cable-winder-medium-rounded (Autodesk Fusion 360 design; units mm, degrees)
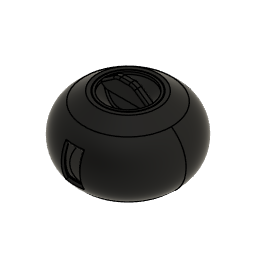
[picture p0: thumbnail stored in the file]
parameter "radius" = 30
parameter "height" = 40
parameter "gap" = 0.35
sketch "Skizze" plane through (0, 0, 0) normal (0, 1, 0) x axis (1, 0, 0)
  line L1 (30, 0) -> (0, 0)
  line L2 (14, -20) -> (16, -20)
  line L3 (14, -18.9589) -> (22, -13.3572)
  line L4 (14, -18.9589) -> (14, -20)
  line L5 (12.45, -20) -> (13.65, -20)
  line L6 (13.65, -18.7767) -> (13.65, -20)
  line L7 (15.6652, -17.3656) -> (13.65, -18.7767)
  line L8 (8, -11.9984) -> (15.6652, -17.3656)
  line L9 (8, 0) -> (8, -11.9984)
  line L10 (12.45, -18.7767) -> (12.45, -20)
  line L11 (5.626, -13.9984) -> (12.45, -18.7767)
  line L12 (0, -13.9984) -> (5.626, -13.9984)
  line L13 (12.45, -18.7767) -> (13.65, -18.7767)
  line L14 (0, 0) -> (0, -13.9984)
  line L15 (0, -20) -> (0, -13.9984)
  line L16 (12.45, -20) -> (0, -20)
  line L17 (0, -11.9984) -> (8, -11.9984)
  line L18 (15.3795, -17.1656) -> (15.3795, -17.5656)
  line L19 (0, 0) -> (0, 13.9984)
  line L20 (0, 11.9984) -> (8, 11.9984)
  line L21 (8, 0) -> (8, 11.9984)
  line L22 (8, 11.9984) -> (15.6652, 17.3656)
  line L23 (12.45, 20) -> (13.65, 20)
  line L24 (0, 20) -> (0, 13.9984)
  line L25 (12.45, 20) -> (0, 20)
  line L26 (13.65, 18.7767) -> (13.65, 20)
  line L27 (15.6652, 17.3656) -> (13.65, 18.7767)
  line L28 (14, 18.9589) -> (14, 20)
  line L29 (14, 20) -> (16, 20)
  line L30 (14, 18.9589) -> (22, 13.3572)
  line L31 (-2, -13.9984) -> (2, -13.9984)
  line L32 (4.4501, -25.6016) -> (12.45, -20)
  line L33 (0, -25.6016) -> (4.4501, -25.6016)
  line L34 (12.45, 18.7767) -> (12.45, 20)
  line L35 (5.626, 13.9984) -> (12.45, 18.7767)
  line L36 (0, 13.9984) -> (5.626, 13.9984)
  line L37 (-4.4501, -25.6016) -> (-12.45, -20)
  line L38 (0, -25.6016) -> (-4.4501, -25.6016)
  line L39 (-5.626, -13.9984) -> (-12.45, -18.7767)
  line L40 (-12.45, -18.7767) -> (-12.45, -20)
  line L41 (0, -13.9984) -> (-5.626, -13.9984)
  line L42 (0, 13.9984) -> (-5.626, 13.9984)
  line L43 (-5.626, 13.9984) -> (-12.45, 18.7767)
  line L44 (-12.45, 18.7767) -> (-12.45, 20)
  line L45 (-12.45, 20) -> (0, 20)
  line L46 (4, -8) -> (-4, -8)
  line L47 (4, 8) -> (4, -8)
  line L48 (-4, 8) -> (4, 8)
  line L49 (-4, -8) -> (-4, 8)
  line L50 (4, 8) -> (-4, -8)
  line L51 (-4, 8) -> (4, -8)
  curve K1 (22, 13.3572) -> (22, -13.3572)
  line L52 (16, -20) -> (23.1472, -14.9955)
  curve K2 (23.1472, 14.9955) -> (23.1472, -14.9955)
  line L53 (16, 20) -> (23.1472, 14.9955)
  point P1 (0, 0)
  point P2 (0, 0)
  point P12 (8, 0)
  point P17 (0, 0)
  point P19 (0, -11.9984)
  point P20 (15.3795, -17.5656)
  point P21 (15.3795, -17.1656)
  point P24 (0, 0)
  point P28 (0, 0)
  point P4 (16, -20)
  point P37 (16, 20)
  point P5 (22, -13.3572)
  point P38 (22, 13.3572)
  point P6 (14, -20)
  point P35 (14, 20)
  point P7 (14, -18.9589)
  point P36 (14, 18.9589)
  point P8 (13.65, -20)
  point P31 (13.65, 20)
  point P9 (13.65, -18.7767)
  point P34 (13.65, 18.7767)
  point P10 (15.6652, -17.3656)
  point P30 (15.6652, 17.3656)
  point P11 (8, -11.9984)
  point P23 (8, 11.9984)
  point P29 (8, 0)
  point P13 (12.45, -20)
  point P32 (12.45, 20)
  point P15 (5.626, -13.9984)
  point P27 (5.626, 13.9984)
  point P16 (0, -13.9984)
  point P22 (0, 13.9984)
  point P26 (0, 0)
  point P18 (0, -20)
  point P33 (0, 20)
  point P25 (0, 11.9984)
  point P41 (0, -20)
  point P44 (12.45, 20)
  point P14 (12.45, -18.7767)
  point P45 (12.45, 18.7767)
  point P46 (5.626, 13.9984)
  point P47 (0, 13.9984)
  point P48 (-12.45, -20)
  point P51 (-12.45, -18.7767)
  point P52 (-5.626, -13.9984)
  point P53 (0, -13.9984)
  point P42 (4.4501, -25.6016)
  point P49 (-4.4501, -25.6016)
  point P43 (0, -25.6016)
  point P50 (0, -25.6016)
  point P59 (-12.45, 20)
  point P58 (0, 20)
  point P57 (-12.45, 20)
  point P56 (-12.45, 18.7767)
  point P54 (-5.626, 13.9984)
  point P55 (0, 13.9984)
  point P64 (0, 0)
  point P3 (30, 0)
  point P62 (4, 8)
  point P63 (-4, 8)
  point P61 (4, -8)
  coincident P1 P2
  horizontal L1
  perpendicular L2 L4
  perpendicular L4 L5
  perpendicular L5 L6
  parallel L3 L7
  coincident L1 P12
  perpendicular L1 L9
  perpendicular L5 L10
  parallel L8 L11
  horizontal L13
  collinear L2 L5
  coincident P1 P17
  perpendicular L1 L14
  perpendicular L5 L15
  perpendicular L10 L16
  coincident L14 P19
  perpendicular L14 L17
  coincident L7 P20
  coincident L8 P21
  vertical L18
  symmetric P1 L1 P24
  symmetric P2 L1 P28
  symmetric L1 P4 P37
  symmetric L1 P5 P38
  symmetric L1 P6 P35
  symmetric L1 P7 P36
  symmetric L1 P8 P31
  symmetric L1 P9 P34
  symmetric L1 P10 P30
  symmetric L1 P11 P23
  symmetric L1 P12 P29
  symmetric L1 P13 P32
  symmetric L1 P15 P27
  symmetric L1 P16 P22
  symmetric L1 P17 P26
  symmetric L1 P18 P33
  symmetric L1 P19 P25
  horizontal L31
  coincident P18 P41
  collinear L12 L31
  perpendicular L15 L33
  symmetric L1 P13 P44
  symmetric L1 P14 P45
  symmetric L1 P15 P46
  symmetric L1 P16 P47
  symmetric P13 L15 P48
  symmetric P14 L15 P51
  symmetric P15 L15 P52
  symmetric P16 L15 P53
  symmetric L15 P42 P49
  symmetric L15 P43 P50
  symmetric P32 L24 P59
  symmetric P33 L24 P58
  symmetric L24 P44 P57
  symmetric L24 P45 P56
  symmetric L24 P46 P54
  symmetric L24 P47 P55
  horizontal L46
  perpendicular L46 L47
  parallel L46 L48
  parallel L47 L49
  coincident L50 P64
  coincident L51 P64
  coincident P28 P64
  dimension "d43" distance P2 P3 = 30 (= "radius")
  dimension "d49" distance P4 L4 = 2
  dimension "d50" distance L4 L6 = 0.35 (= "gap")
  dimension "d51" distance L3 L7 = 0.35 (= "d50")
  dimension "d52" angle L1 L8 = 35
  dimension "d54" distance L8 L11 = 3
  dimension "d55" distance P8 P13 = 1.2
  dimension "d57" distance P4 P16 = 16
  dimension "d58" distance L1 L16 = 20 (= "height / 2")
  dimension "d59" distance L12 L17 = 2
  dimension "d60" distance P20 P21 = 0.4
  dimension "d61" distance L9 L14 = 8
  dimension "d69" angle L16 L32 = 35
  dimension "d70" distance L16 L33 = 5.6016 (= "d71 - 0.4 mm")
  dimension "d71" distance L12 L16 = 6.0016
  dimension "d84" distance P62 P63 = 8
  dimension "d85" distance P61 P62 = 16
  dimension "d141" angle L3 L14 = 55
  dimension "d142" distance P5 P7 = 8
  dimension "d143" = 2
revolve "Drehen1" sketch "Skizze" AlongAngle 360 bodies "Core"
revolve "Drehen1" sketch "Skizze" AlongAngle 360 bodies "Ring"
ground "Fixieren"
joint "Zusammenfügen" alignAngle 0 alignOffsetX 0 alignOffsetY 0 alignOffsetZ 0
chamfer "Fase1" distance 3 Rotate Angle 45
extrude "Extrusion3" cut sketch "Skizze" profile of L24 L25 L34 L35 L36 L42 L43 L44 L45 distance 4
extrude "Extrusion4" add sketch "Skizze" profile of L10 L11 L12 L15 L16 L31 L32 L33 L37 L38 L39 L40 L41 distance 4
chamfer "Fase2" distance 3 Rotate Angle 45
fillet "Abrundung1" radius 1 6
fillet "Abrundung2" radius 4
fillet "Abrundung5" radius 20
extrude "Extrusion5" cut sketch "Skizze" profile of L1 L14 L17 L19 L20 L46 L47 L48 L49 no distance stored
fillet "Abrundung3" radius 1
fillet "Abrundung1" radius 0.8
fillet "Abrundung4" radius 1
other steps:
extrude "Extrusion1" cut sketch "Skizze" profile of L1 L14 L17 L19 L20 L46 L47 L48 L49 no distance stored
create_component "Komponente erstellen1"
create_component "Komponente erstellen2"
joint_origin "Gelenkursprung2"
joint_origin "Gelenkursprung2"
named bodies: "Core", "Ring"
